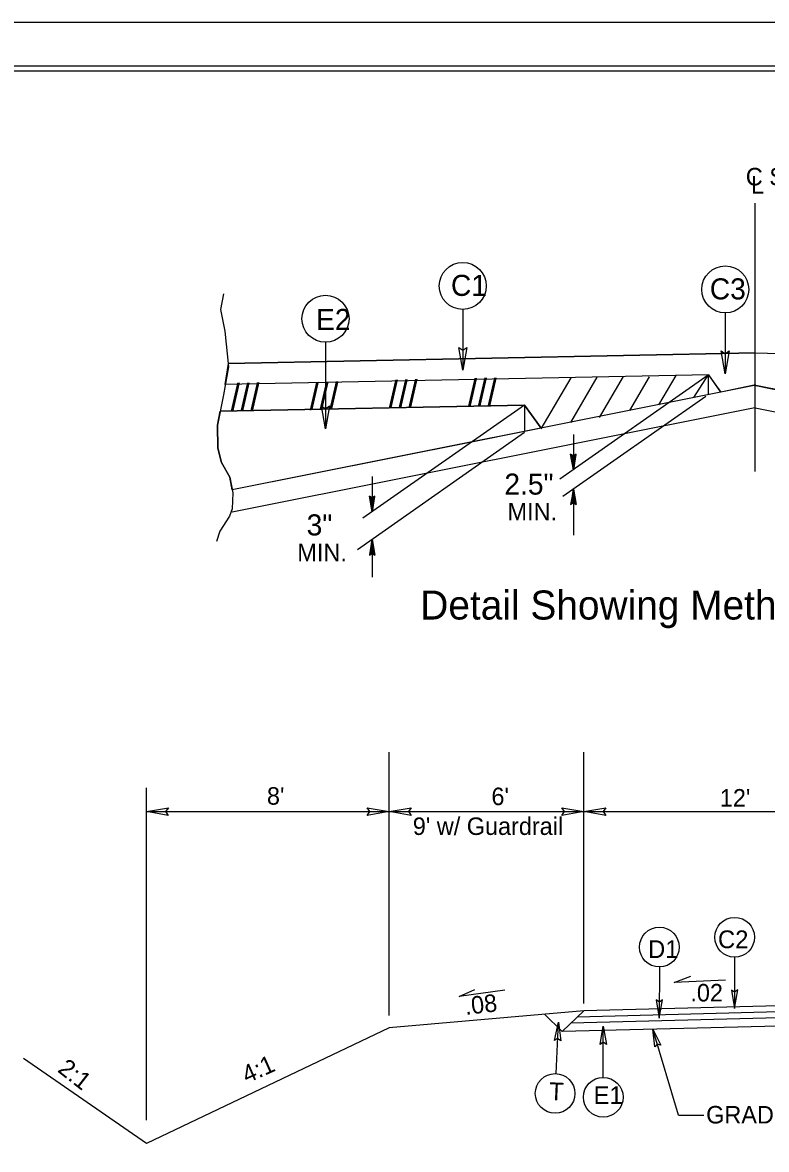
# Model space of a CAD drawing. Extents: x 193555 to 203883, y 190245 to 194645.
# Drawn here: x 196523 to 198052, y 192328 to 194645 of the extents above; entities that cross this region are included whole.
import ezdxf

# ---------------------------------------------------------------- set-up
doc = ezdxf.new("R2010")
doc.units = 0
for name, color, linetype in [('Old_Level_1', 7, 'Continuous'), ('Old_Level_11', 7, 'Continuous'), ('Old_Level_18', 7, 'Continuous'), ('Old_Level_20', 7, 'Continuous'), ('Old_Level_50', 7, 'Continuous'), ('Old_Level_51', 7, 'Continuous'), ('Prop Terminator CELL', 7, 'Continuous'), ('Typical Detail Wedge2 CELL', 7, 'Continuous'), ('Typical ID Circle CELL', 7, 'Continuous'), ('Typical Terminator CELL', 7, 'Continuous'), ('Typical Text Centerline CELL', 7, 'Continuous'), ('Typical Text General CELL', 7, 'Continuous'), ('Typical Text ID Circle CELL', 7, 'Continuous')]:
    doc.layers.add(name, color=color, linetype=linetype)

msp = doc.modelspace()

# ---------------------------------------------------------------- linework, layer by layer
at = {"layer": 'Old_Level_1'}
for p, q in [((197276.4, 192603.5), (197276.4, 193145.1)), ((197676.4, 192628.6), (197676.4, 193145.1)), ((196777.7, 192388.2), (196777.7, 193071.7)), ((197676.4, 192628.6), (197676.4, 193071.7)), ((196777.7, 193022.8), (197276.4, 193022.8)), ((197276.4, 193022.8), (197676.4, 193022.8)), ((197676.4, 193022.8), (198276.4, 193022.8)), ((197861.7, 192671.3), (197895.9, 192684.3)), ((197967.4, 192676.2), (197861.7, 192671.3)), ((197420.1, 192642.6), (197452.7, 192657.2)), ((197514.4, 192655.6), (197420.1, 192642.6)), ((198276.4, 192628.6), (197676.4, 192613.4)), ((197676.4, 192613.4), (197276.4, 192578.5)), ((197631.9, 192570.6), (197595.6, 192606.3)), ((197676.4, 192613.4), (197631.9, 192570.6)), ((198277, 192603.6), (197649.7, 192587.7)), ((198276.7, 192616.1), (197663, 192600.5)), ((197276.4, 192578.5), (196777.7, 192340.2)), ((198277.5, 192587), (197631.9, 192570.6)), ((197870.9, 192398.7), (197818.1, 192575.3)), ((196777.7, 192340.2), (196525.4, 192515.4)), ((197870.9, 192398.7), (197922.6, 192398.7))]:
    msp.add_line(p, q, dxfattribs=at)
at = {"layer": 'Old_Level_11'}
for p, q in [((197986.2, 192723.7), (197986.1, 192618.2)), ((197831.5, 192703.5), (197831.4, 192598)), ((197619.2, 192484.2), (197624.1, 192589.6)), ((197716.1, 192476.4), (197716.1, 192581.9))]:
    msp.add_line(p, q, dxfattribs=at)
for points in [[(196822.7, 193015), (196777.7, 193022.8), (196822.9, 193030.7), (196817.2, 193022.7)], [(197231.4, 193030.5), (197276.4, 193022.8), (197231.1, 193014.8), (197236.9, 193022.8)], [(197321.4, 193015), (197276.4, 193022.8), (197321.7, 193030.7), (197315.9, 193022.7)], [(197631.4, 193030.5), (197676.4, 193022.8), (197631.1, 193014.8), (197636.9, 193022.8)], [(197721.4, 193015), (197676.4, 193022.8), (197721.7, 193030.7), (197715.9, 193022.7)], [(197979.6, 192656), (197986.1, 192618.2), (197992.9, 192656.2), (197986.1, 192651.4)], [(197825, 192635.8), (197831.4, 192598), (197838.2, 192636), (197831.5, 192631.2)], [(197615.8, 192552.1), (197624.1, 192589.6), (197629, 192551.3), (197622.6, 192556.4)], [(197709.6, 192544.1), (197716.1, 192581.9), (197722.8, 192543.9), (197716.1, 192548.7)]]:
    msp.add_lwpolyline(points, close=True, dxfattribs=at)
for centre in [(197831.5, 192744.3), (197986.2, 192764.5), (197617.4, 192443.4), (197716.2, 192435.6)]:
    msp.add_circle(centre, 40.8, dxfattribs=at)
at = {"layer": 'Old_Level_18'}
msp.add_lwpolyline([(200223.1, 194544.8), (194223.1, 194544.8), (194223.1, 190344.8), (200223.1, 190344.8)], close=True, dxfattribs=at)
at = {"layer": 'Old_Level_50'}
msp.add_lwpolyline([(200273.1, 194555), (193607.1, 194555), (193607.1, 190334.6), (200273.1, 190334.6)], close=True, dxfattribs=at)
at = {"layer": 'Old_Level_51'}
msp.add_lwpolyline([(200291.1, 194644.8), (193555.1, 194644.8), (193555.1, 190244.8), (200291.1, 190244.8)], close=True, dxfattribs=at)
at = {"layer": 'Prop Terminator CELL'}
msp.add_lwpolyline([(197822.5, 192539), (197818.1, 192575.3), (197834.6, 192542.4), (197827.2, 192545)], close=True, dxfattribs=at)
at = {"layer": 'Typical Detail Wedge2 CELL'}
for p, q in [((198028.2, 193722), (198028.2, 194273.4)), ((198028.2, 193722), (198028.2, 194098.6)), ((198028.2, 193965.6), (196946, 193944)), ((196946, 193944), (198028.2, 193965.6)), ((198028.2, 193965.6), (199110.5, 193944)), ((198028.3, 193965.6), (199110.5, 193944)), ((196939.8, 193900.5), (196946, 193944)), ((197933.2, 193920.4), (196939.8, 193900.5)), ((197933.2, 193920.4), (196939.8, 193900.5)), ((197932, 193919.6), (197627.1, 193706)), ((197865.1, 193919.5), (197829.8, 193859)), ((197902.5, 193874.1), (197931.9, 193920)), ((197931.9, 193920), (197931.9, 193879.5)), ((197957.6, 193884.7), (197933.2, 193920.4)), ((197933.2, 193919.2), (197957.6, 193884.7)), ((198029.8, 193899.1), (196954.1, 193683.9)), ((197649.4, 193914.7), (197587.9, 193809.3)), ((197703.4, 193915.8), (197649, 193822.4)), ((197756.9, 193916.9), (197708, 193833.1)), ((197810.8, 193916.7), (197770.2, 193847.4)), ((198026.6, 193899.1), (197957.6, 193884.7)), ((198026.6, 193899.1), (199102.3, 193683.9)), ((198098.8, 193884.7), (198026.6, 193899.1)), ((197926.8, 193876), (197633.5, 193670.6)), ((197554.8, 193858.6), (196929.3, 193846)), ((196929.3, 193846), (197554.8, 193858.6)), ((198027.8, 193852.8), (196953.7, 193638)), ((197554.8, 193858.6), (197222.6, 193626)), ((197588.8, 193810.7), (197554.8, 193858.6)), ((197554.8, 193858.6), (197554.8, 193804)), ((197554.8, 193858.6), (197588.7, 193810.9)), ((198028.6, 193852.8), (199105.2, 193637.4)), ((197554.8, 193804.1), (197445.8, 193782.3)), ((197588.7, 193810.9), (197554.8, 193804.1)), ((197445.8, 193782.3), (196954.1, 193683.9)), ((197554.5, 193802.3), (197211.1, 193560.7)), ((197654.9, 193798.1), (197654.9, 193725.5)), ((197654.9, 193725.5), (197649.3, 193757.3)), ((197654.9, 193753.2), (197649.3, 193757.3)), ((197654.9, 193725.5), (197660.5, 193757.3)), ((197660.5, 193757.3), (197654.9, 193753.2)), ((197654.9, 193725.5), (197650.1, 193756.7)), ((197650.9, 193756.1), (197654.9, 193725.5)), ((197654.9, 193725.5), (197651.6, 193755.6)), ((197652.5, 193755), (197654.9, 193725.5)), ((197654.9, 193725.5), (197653.3, 193754.4)), ((197654.1, 193753.8), (197654.9, 193725.5)), ((197659.7, 193756.7), (197654.9, 193725.5)), ((197654.9, 193725.5), (197658.8, 193756.1)), ((197658.1, 193755.6), (197654.9, 193725.5)), ((197654.9, 193725.5), (197657.3, 193755)), ((197656.5, 193754.4), (197654.9, 193725.5)), ((197654.9, 193725.5), (197655.7, 193753.8)), ((197654.9, 193753.2), (197654.9, 193725.5)), ((197241.3, 193711.4), (197241.3, 193639)), ((197241.3, 193639), (197235.7, 193670.9)), ((197241.3, 193666.8), (197235.7, 193670.9)), ((197241.3, 193639), (197236.5, 193670.3)), ((197237.4, 193669.7), (197241.3, 193639)), ((197241.3, 193639), (197238.2, 193669.1)), ((197239, 193668.6), (197241.3, 193639)), ((197241.3, 193639), (197239.8, 193668)), ((197240.5, 193667.4), (197241.3, 193639)), ((197241.3, 193639), (197247, 193670.9)), ((197247, 193670.9), (197241.3, 193666.8)), ((197246.2, 193670.3), (197241.3, 193639)), ((197241.3, 193639), (197245.4, 193669.7)), ((197244.6, 193669.1), (197241.3, 193639)), ((197241.3, 193639), (197243.7, 193668.6)), ((197243, 193668), (197241.3, 193639)), ((197241.3, 193639), (197242.1, 193667.4)), ((197241.3, 193666.8), (197241.3, 193639)), ((197654.9, 193685.6), (197649.3, 193653.8)), ((197650.1, 193654.4), (197654.9, 193685.6)), ((197654.9, 193685.6), (197650.9, 193654.9)), ((197651.6, 193655.6), (197654.9, 193685.6)), ((197654.9, 193685.6), (197652.5, 193656.1)), ((197653.3, 193656.7), (197654.9, 193685.6)), ((197654.9, 193685.6), (197654.1, 193657.3)), ((197654.9, 193685.6), (197654.9, 193591.2)), ((197654.9, 193685.6), (197660.5, 193653.8)), ((197654.9, 193657.9), (197654.9, 193685.6)), ((197655.7, 193657.3), (197654.9, 193685.6)), ((197654.9, 193685.6), (197656.5, 193656.7)), ((197657.3, 193656.1), (197654.9, 193685.6)), ((197654.9, 193685.6), (197658.1, 193655.6)), ((197658.8, 193654.9), (197654.9, 193685.6)), ((197654.9, 193685.6), (197659.7, 193654.4)), ((197649.3, 193653.8), (197654.9, 193657.9)), ((197654.9, 193657.9), (197660.5, 193653.8)), ((197241.3, 193581.8), (197235.7, 193550)), ((197236.6, 193550.6), (197241.3, 193581.8)), ((197241.3, 193581.8), (197237.4, 193551.2)), ((197238.2, 193551.8), (197241.3, 193581.8)), ((197241.3, 193581.8), (197239, 193552.4)), ((197239.8, 193552.9), (197241.3, 193581.8)), ((197241.3, 193581.8), (197240.5, 193553.5)), ((197241.3, 193581.8), (197241.3, 193504.5)), ((197241.3, 193581.8), (197247, 193550)), ((197241.3, 193554.1), (197241.3, 193581.8)), ((197242.1, 193553.5), (197241.3, 193581.8)), ((197241.3, 193581.8), (197243, 193552.9)), ((197243.8, 193552.4), (197241.3, 193581.8)), ((197241.3, 193581.8), (197244.6, 193551.8)), ((197245.4, 193551.2), (197241.3, 193581.8)), ((197241.3, 193581.8), (197246.2, 193550.6)), ((197235.7, 193550), (197241.3, 193554.1)), ((197241.3, 193554.1), (197247, 193550))]:
    msp.add_line(p, q, dxfattribs=at)
for points in [[(196935.9, 194086.9), (196930.1, 194055.1), (196938.8, 194010.1), (196946.5, 193937.1), (196935.9, 193879.5), (196923.5, 193817.1), (196924.4, 193770), (196932.1, 193740.3), (196949.4, 193710.5), (196955.1, 193677.9), (196954.2, 193645.3), (196948.4, 193629.9), (196928.3, 193599.2), (196921.5, 193578)], [(196954.1, 193683.9), (196949.4, 193710.5), (196932.1, 193740.3), (196924.4, 193770), (196923.5, 193817.1), (196929.2, 193846)]]:
    msp.add_lwpolyline(points, dxfattribs=at)
at = {"layer": 'Typical ID Circle CELL'}
for p, q in [((197427.7, 194054.9), (197427.7, 193930)), ((197967, 194047.8), (197967, 193922.9)), ((197145.7, 193987.5), (197145.7, 193809.9))]:
    msp.add_line(p, q, dxfattribs=at)
for centre in [(197427.7, 194103.3), (197967, 194096.2), (197145.6, 194035.8)]:
    msp.add_circle(centre, 48.3, dxfattribs=at)
at = {"layer": 'Typical Terminator CELL'}
for points in [[(197435.8, 193976.9), (197427.7, 193930), (197419.4, 193977.1), (197427.7, 193971.2)], [(197435.8, 193976.9), (197427.7, 193930), (197419.4, 193977.1), (197427.7, 193971.2)], [(197975.1, 193969.8), (197967, 193922.9), (197958.7, 193970), (197967, 193964.1)], [(197975.1, 193969.8), (197967, 193922.9), (197958.7, 193970), (197967, 193964.1)], [(197153.7, 193856.7), (197145.7, 193809.9), (197137.3, 193857), (197145.7, 193851)], [(197153.7, 193856.7), (197145.7, 193809.9), (197137.3, 193857), (197145.7, 193851)]]:
    msp.add_lwpolyline(points, close=True, dxfattribs=at)

# ---------------------------------------------------------------- texts
at = {"layer": 'Old_Level_1'}
for s, p in [("8'", (197025.3, 193037)), ("6'", (197486.5, 193036.1)), ("12'", (197955.8, 193033.1)), ("9' w/ Guardrail", (197325, 192974.8)), ('.02', (197895.3, 192632.5)), ('GRADE TO THIS LINE', (197927.7, 192381.7))]:
    msp.add_text(s, height=36, dxfattribs=at).set_placement(p)
for s, rotation, p in [('.08', 6.504, (197433.5, 192604.8)), ('2:1', 321.9623, (196593.3, 192489.3)), ('4:1', 24.0762, (196984.1, 192463.5))]:
    msp.add_text(s, height=36, rotation=rotation, dxfattribs=at).set_placement(p)
at = {"layer": 'Old_Level_20'}
for s, height, rotation, p in [('C2', 36.54, 359.9708, (197952, 192742)), ('D1', 36.54, 359.9708, (197808.3, 192721.8)), ('T', 36.5, 357.375, (197604.4, 192430)), ('E1', 36.54, 0.0292, (197696.5, 192421.6))]:
    msp.add_text(s, height=height, rotation=rotation, dxfattribs=at).set_placement(p)
at = {"layer": 'Typical Detail Wedge2 CELL'}
for height, rotation, p in [(54.27, 1.1447, (196950.8, 193846.8)), (54.27, 1.1464, (197113, 193848.7)), (54.25, 1.1445, (197275.6, 193853.5)), (54.25, 1.1463, (197438.3, 193856.8))]:
    msp.add_text('/// ', height=height, rotation=rotation, dxfattribs=at).set_placement(p)
for s, height, p in [('2.5"', 43.27, (197513.1, 193674.4)), ('MIN.', 36.15, (197519.5, 193621.2)), ('3"', 43.27, (197106.9, 193590.5)), ('MIN.', 36.15, (197087.6, 193537.3))]:
    msp.add_text(s, height=height, dxfattribs=at).set_placement(p)
at = {"layer": 'Typical Text Centerline CELL'}
for s, height, p in [('C SURVEY ', 36.15, (198009.1, 194309.9)), ('L', 36.2, (198019.7, 194292.9))]:
    msp.add_text(s, height=height, dxfattribs=at).set_placement(p)
at = {"layer": 'Typical Text General CELL'}
msp.add_text('Detail Showing Method of Wedging', height=59.678, dxfattribs=at).set_placement((197340.4, 193417.6))
at = {"layer": 'Typical Text ID Circle CELL'}
for s, p in [('C1', (197403.4, 194082.9)), ('C3', (197935.2, 194075.7)), ('E2', (197126.2, 194012.8))]:
    msp.add_text(s, height=43.27, dxfattribs=at).set_placement(p)

doc.saveas('drawing.dxf')
